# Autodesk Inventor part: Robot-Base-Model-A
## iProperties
Shininess: 21.0
Length Units: 11269
Angle Units: 11279
Time Units: 11290
Mass Units: 11283
Length Display Precision: 3
Angle Display Precision: 2
Created: 2001-08
Part Number: Robot-Base-Model-A
Document SubType Name: ﾓﾃﾞﾘﾝｸﾞ
Designer: Administrator
Density: 1 g/cm^3
Density: 0.0
Volumn: 0.0
Area: 0.0
PropertySet Name: Model Information
Control State: 0
Master: False
Checked Out: False
Author: Administrator
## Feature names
1. Extrusion1
2. Extrusion2
3. Extrusion3
4. FaceDraft
5. Chamfer1 [Fillet]
6. Chamfer2 [Fillet]
7. Chamfer3 [Fillet]
8. Hole1
9. Chamfer4 [Fillet]
10. Extrusion4
11. Shell1
